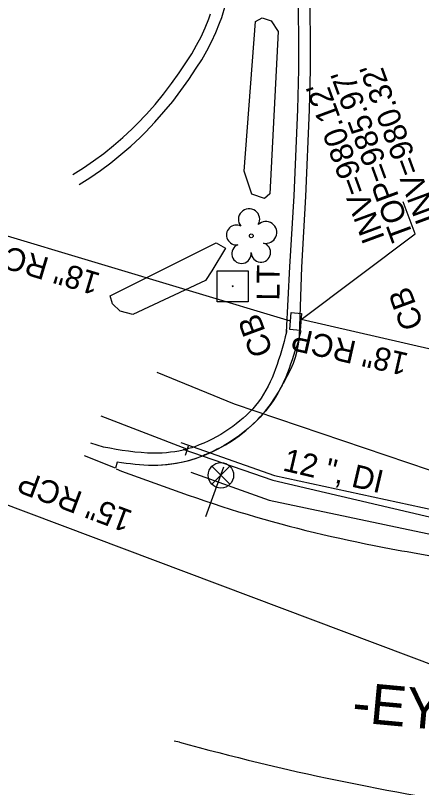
# Model space of a CAD drawing. Extents: x 1614611 to 1617571, y 898867 to 905462.
# Drawn here: x 1615825.7 to 1615896.7, y 904021.8 to 904156.5 of the extents above; entities that cross this region are included whole.
import ezdxf

# ---------------------------------------------------------------- set-up
doc = ezdxf.new("R2010")
doc.units = 0
for name, color, linetype in [('Exist Boundary Watershed Impervious C 09', 7, 'Continuous'), ('Exist Boundary Watershed Residential C 05', 7, 'Continuous'), ('Exist Structure Minor Catch Basin Top Elevation', 7, 'Continuous'), ('Exist Structure Minor Pipes RCP 18 Inch Invert', 7, 'Continuous'), ('Exist Utilities Gas UG Line SUE LOS B', 7, 'Continuous'), ('Exist Utilities Other Pole With Base CELL', 7, 'Continuous'), ('Exist Utilities Other Pole With Base Text', 7, 'Continuous'), ('Exist Utilities Telephone UG FO SUE LOS B', 7, 'Continuous'), ('Exist Utilities Water UG Line SUE LOS B', 7, 'Continuous'), ('Exist Utilities Water UG Line SUE LOS B Text', 7, 'Continuous'), ('Exist Vegetation Hedge Row', 7, 'Continuous'), ('Exist Vegetation Tree CELL', 7, 'Continuous'), ('Prop Drainage Structure Catch Basin Adjust Label', 7, 'Continuous'), ('Prop Drainage Structure Catch Basin Grate 840 03E Label', 7, 'Continuous'), ('Prop Drainage Structure Catch Basin Open Throat 4 CELL', 7, 'Continuous'), ('Prop Drainage Structure Drop Inlet Grate 3 Narrow Slots and Sag Grates 840 24 Label', 7, 'Continuous'), ('Prop Earthen Structure V Ditch Detail Label', 7, 'Continuous'), ('Prop Easement Permanent Drainage', 7, 'Continuous'), ('Prop Erosion Embankment Toe Protection with Rip Rap 2 Detail CELL', 7, 'Continuous'), ('Prop Erosion Embankment Toe Protection with Rip Rap 3 Detail CELL', 7, 'Continuous'), ('Prop Plan Preparation Drainage Notes Label', 7, 'Continuous'), ('Prop Plan Preparation Table Ditch Data CELL', 7, 'Continuous'), ('Scratch_Level_1', 7, 'Continuous'), ('Scratch_Level_9', 7, 'Continuous')]:
    doc.layers.add(name, color=color, linetype=linetype)

# ---------------------------------------------------------------- blocks, each defined once
blk = doc.blocks.new('EXIST UTILITIES WATER VALVE')
at = {"layer": 'Prop Earthen Structure V Ditch Detail Label'}
blk.add_lwpolyline([(0.0315, 0.0315), (-0.0315, -0.0315), (0, 0), (0.0315, -0.0315), (-0.0315, 0.0315)], dxfattribs=at)
blk.add_circle((0, 0), 0.0445, dxfattribs=at)

msp = doc.modelspace()

# ---------------------------------------------------------------- linework, layer by layer
at = {"layer": 'Exist Boundary Watershed Impervious C 09'}
for p, q in [((1615843.29, 904077.41), (1615844.2, 904077.02)), ((1615854.37, 904029.72), (1615853.45, 904029.9))]:
    msp.add_line(p, q, dxfattribs=at)
msp.add_ellipse((1615972.71, 904454.31), major_axis=(399.48, 187.91), ratio=0.997263, start_param=4.002237, end_param=4.130845, dxfattribs=at)
msp.add_spline([(1615844.2, 904077.02), (1615867.65, 904069.04), (1615891.35, 904063.48), (1615906.39, 904061.04), (1615912.51, 904060.26)], degree=3, dxfattribs=at)
at = {"layer": 'Exist Boundary Watershed Residential C 05'}
for p, q in [((1615873.09, 904101.7), (1615873.06, 904101.28)), ((1615841.08, 904081.2), (1615838.85, 904081.9))]:
    msp.add_line(p, q, dxfattribs=at)
for points in [[(1615873.06, 904101.28), (1615873.63, 904112.68), (1615874.39, 904125.07), (1615875.04, 904140.12), (1615875.19, 904147.13), (1615875.17, 904162.5), (1615874.94, 904173.09), (1615874.35, 904186.53), (1615873.89, 904193.95), (1615873.05, 904204.18), (1615872.42, 904211.71), (1615871.45, 904220.8), (1615870.59, 904227.98), (1615869.39, 904236.37), (1615866.57, 904254.69)], [(1615836.81, 904127.04), (1615838.69, 904128.23), (1615840.55, 904129.51), (1615842.36, 904130.85), (1615844.13, 904132.26), (1615845.84, 904133.73), (1615847.49, 904135.26), (1615848.44, 904136.19), (1615850.08, 904137.92), (1615851.65, 904139.71), (1615853.17, 904141.54), (1615854.61, 904143.43), (1615856, 904145.36), (1615857.29, 904147.32), (1615858.24, 904148.8), (1615859.14, 904150.35), (1615859.96, 904151.94), (1615860.71, 904153.57), (1615861.38, 904155.22), (1615861.74, 904156.19), (1615862.4, 904158.42)]]:
    msp.add_lwpolyline(points, dxfattribs=at)
msp.add_spline([(1615873.06, 904101.28), (1615868.15, 904089.1), (1615863.66, 904084.81), (1615857.82, 904081.58), (1615855.69, 904080.86), (1615849.88, 904080.14), (1615841.08, 904081.2)], degree=3, dxfattribs=at)
at = {"layer": 'Exist Utilities Gas UG Line SUE LOS B'}
for points in [[(1615854.58, 904082), (1615870.95, 904076.26), (1615903.3, 904069.25), (1615940.35, 904064.34), (1615960.08, 904063.22), (1615980.19, 904063.57), (1616009.39, 904069.59), (1616033.23, 904075.98), (1616065.79, 904088.71), (1616071.64, 904092.21), (1616080.09, 904108.75), (1616091.42, 904131.52), (1616096.21, 904140.27), (1616099.08, 904143.48), (1616102.9, 904146.03), (1616112.33, 904149.72)], [(1615855.89, 904081.36), (1615855.35, 904079.73)]]:
    msp.add_lwpolyline(points, dxfattribs=at)
at = {"layer": 'Exist Utilities Other Pole With Base CELL'}
msp.add_line((1615863.66, 904109.28), (1615863.66, 904109.28), dxfattribs=at)
msp.add_lwpolyline([(1615860.94, 904111.98), (1615866.34, 904111.98), (1615866.34, 904106.58), (1615860.94, 904106.58), (1615860.94, 904111.98)], dxfattribs=at)
msp.add_circle((1615863.66, 904109.28), 0.0707, dxfattribs=at)
at = {"layer": 'Exist Utilities Telephone UG FO SUE LOS B'}
msp.add_lwpolyline([(1615856.34, 904076.83), (1615870.05, 904071.95), (1615904.01, 904064.8), (1615940.09, 904061.28), (1615960.29, 904059.81), (1615980.62, 904060.75), (1616010.57, 904065.68), (1616034.12, 904072.52), (1616066.45, 904085.29), (1616094.72, 904098.79), (1616101.16, 904102.54), (1616107.05, 904108.53), (1616109.46, 904114.97), (1616109.89, 904122.41), (1616109.17, 904135.16), (1616109.54, 904138.63), (1616110.42, 904139.78), (1616119.05, 904144.94), (1616144.14, 904158.05), (1616163.63, 904162.04), (1616171.06, 904164.3), (1616173.72, 904166.8)], dxfattribs=at)
at = {"layer": 'Exist Utilities Water UG Line SUE LOS B'}
for points in [[(1615854.96, 904080.87), (1615870.68, 904075.46), (1615903.78, 904067.73), (1615940.26, 904062.7), (1615960.04, 904061.3), (1615980.56, 904061.76), (1616010.46, 904066.89), (1616033.97, 904071.93), (1616069.14, 904081.95), (1616099.73, 904091.26), (1616134.12, 904102.78), (1616151.27, 904109.12), (1616173.83, 904118)], [(1615858.99, 904069.08), (1615862.1, 904077.77)]]:
    msp.add_lwpolyline(points, dxfattribs=at)
at = {"layer": 'Exist Vegetation Hedge Row'}
for points in [[(1615866.98, 904125.36), (1615865.64, 904129.37), (1615867.66, 904155.49), (1615868.83, 904156.11), (1615870.36, 904155.6), (1615871.6, 904153.77), (1615870.17, 904125.4), (1615869.21, 904124.61), (1615866.98, 904125.36)], [(1615842.22, 904107.61), (1615860.77, 904116.84), (1615862.38, 904115.95), (1615860.03, 904111.97), (1615858.91, 904110.29), (1615846.2, 904104.35), (1615844, 904104.92), (1615842.68, 904106.22), (1615842.22, 904107.61)]]:
    msp.add_lwpolyline(points, dxfattribs=at)
at = {"layer": 'Exist Vegetation Tree CELL'}
msp.add_line((1615866.91, 904118.08), (1615866.91, 904118.08), dxfattribs=at)
msp.add_circle((1615866.91, 904118.08), 0.326, dxfattribs=at)
for centre, radius, start, end in [((1615866.52, 904120.96), 1.86, 330.1651, 219.7134), ((1615869.46, 904118.67), 1.9, 257.1011, 134.1999), ((1615864.3, 904118.24), 1.73, 62.6636, 279.3457), ((1615865.2, 904114.96), 1.69, 111.5671, 6.231), ((1615868.58, 904115.18), 1.7, 181.2822, 74.56)]:
    msp.add_arc(centre, radius, start, end, dxfattribs=at)
at = {"layer": 'Prop Drainage Structure Catch Basin Grate 840 03E Label'}
msp.add_lwpolyline([(1615850.39, 904094.27), (1615863.9, 904088.79), (1615901.78, 904075.97), (1615940.62, 904069.74), (1615960.64, 904067.69), (1615979.21, 904068.06), (1616007.56, 904076.64), (1616032.56, 904083.45), (1616059.29, 904090.87), (1616085.68, 904100.71), (1616093.61, 904105.52), (1616099.52, 904112.39), (1616102.28, 904129.68), (1616094.33, 904153), (1616085.98, 904178.59), (1616082.67, 904190.98), (1616081.58, 904203.76)], dxfattribs=at)
at = {"layer": 'Prop Drainage Structure Catch Basin Open Throat 4 CELL'}
msp.add_lwpolyline([(1615873.86, 904104.68), (1615875.71, 904104.51), (1615875.46, 904101.54), (1615873.67, 904101.75), (1615873.86, 904104.68)], dxfattribs=at)
at = {"layer": 'Prop Erosion Embankment Toe Protection with Rip Rap 3 Detail CELL'}
for p, q in [((1615873.78, 904103.2), (1615804.66, 904123.9)), ((1615898.71, 904098.2), (1615875.61, 904103.46))]:
    msp.add_line(p, q, dxfattribs=at)
at = {"layer": 'Prop Plan Preparation Drainage Notes Label'}
msp.add_lwpolyline([(1615875.61, 904103.46), (1615895.54, 904118.41), (1615893.47, 904124.04)], dxfattribs=at)
at = {"layer": 'Prop Plan Preparation Table Ditch Data CELL'}
msp.add_line((1615933.05, 904030.25), (1615731.82, 904105.72), dxfattribs=at)
at = {"layer": 'Scratch_Level_1'}
msp.add_line((1615855.64, 904080.86), (1615840.69, 904086.62), dxfattribs=at)
for points in [[(1615850.52, 904078.06), (1615851.93, 904078.15), (1615853.33, 904078.32), (1615854.71, 904078.58), (1615856.08, 904078.9), (1615857.43, 904079.31), (1615858.76, 904079.79), (1615859.83, 904080.25), (1615861.14, 904080.88), (1615862.4, 904081.58), (1615863.63, 904082.35), (1615864.81, 904083.18), (1615865.94, 904084.08), (1615867.02, 904085.04), (1615868.05, 904086.05), (1615868.47, 904086.51), (1615869.39, 904087.56), (1615870.26, 904088.66), (1615871.05, 904089.81), (1615871.79, 904091), (1615872.45, 904092.23), (1615872.52, 904092.38), (1615873.8, 904094.8), (1615874.26, 904095.85), (1615874.64, 904096.93), (1615874.94, 904098.03), (1615875.17, 904099.15), (1615875.32, 904100.28), (1615875.35, 904100.57), (1615875.75, 904112.62), (1615876.44, 904124.97), (1615877.08, 904140.06), (1615877.24, 904147.11), (1615877.21, 904162.52)], [(1615835.72, 904128.77), (1615837.56, 904129.93), (1615839.36, 904131.17), (1615841.12, 904132.47), (1615842.83, 904133.83), (1615844.48, 904135.25), (1615846.08, 904136.74), (1615846.99, 904137.62), (1615848.58, 904139.3), (1615850.1, 904141.03), (1615851.57, 904142.81), (1615852.97, 904144.64), (1615854.32, 904146.52), (1615855.59, 904148.44), (1615856.5, 904149.86), (1615857.35, 904151.33), (1615858.13, 904152.84), (1615858.84, 904154.38), (1615859.48, 904155.95), (1615859.8, 904156.83)]]:
    msp.add_lwpolyline(points, dxfattribs=at)
at = {"layer": 'Scratch_Level_9'}
msp.add_line((1615875.55, 904101.49), (1615875.47, 904101.02), dxfattribs=at)
msp.add_lwpolyline([(1615843.47, 904078.58), (1615843.19, 904077.51), (1615837.77, 904079.69)], dxfattribs=at)
msp.add_spline([(1615875.47, 904101.02), (1615870.72, 904089.28), (1615862.14, 904081.49), (1615858.81, 904079.84), (1615856.29, 904078.93), (1615849.72, 904078), (1615843.47, 904078.58)], degree=3, dxfattribs=at)

# ---------------------------------------------------------------- block references
at = {"layer": 'Prop Earthen Structure V Ditch Detail Label', "xscale": 50, "yscale": 50}
msp.add_blockref('EXIST UTILITIES WATER VALVE', (1615861.6, 904076.29), dxfattribs=at)

# ---------------------------------------------------------------- texts
at = {"layer": 'Exist Structure Minor Catch Basin Top Elevation'}
msp.add_text("TOP=985.97'", height=4, rotation=110.2165, dxfattribs=at).set_placement((1615895.32, 904118))
at = {"layer": 'Exist Structure Minor Pipes RCP 18 Inch Invert'}
for s, p in [("INV=980.32'", (1615899.64, 904121.05)), ("INV=980.12'", (1615890.29, 904117.68))]:
    msp.add_text(s, height=4, rotation=110.2165, dxfattribs=at).set_placement(p)
at = {"layer": 'Exist Utilities Other Pole With Base Text'}
msp.add_text('LT', height=4, rotation=89.4707, dxfattribs=at).set_placement((1615871.83, 904106.76))
at = {"layer": 'Exist Utilities Water UG Line SUE LOS B Text'}
msp.add_text('12 ", DI', height=4, rotation=346.8621, dxfattribs=at).set_placement((1615872.24, 904077.15))
at = {"layer": 'Prop Drainage Structure Catch Basin Adjust Label'}
msp.add_text('-EY6-', height=7, rotation=354.7333, dxfattribs=at).set_placement((1615884.37, 904033.26))
at = {"layer": 'Prop Drainage Structure Drop Inlet Grate 3 Narrow Slots and Sag Grates 840 24 Label'}
for rotation, p in [(163.3289, (1615840.75, 904111.47)), (167.1839, (1615894.58, 904097.52))]:
    msp.add_text('18" RCP', height=4, rotation=rotation, dxfattribs=at).set_placement(p)
at = {"layer": 'Prop Easement Permanent Drainage'}
for p in [(1615897.07, 904102.52), (1615870.76, 904097.82)]:
    msp.add_text('CB', height=4, rotation=110.2165, dxfattribs=at).set_placement(p)
at = {"layer": 'Prop Erosion Embankment Toe Protection with Rip Rap 2 Detail CELL'}
msp.add_text('15" RCP', height=4, rotation=159.4429, dxfattribs=at).set_placement((1615846.4, 904069.96))

doc.saveas('drawing.dxf')
